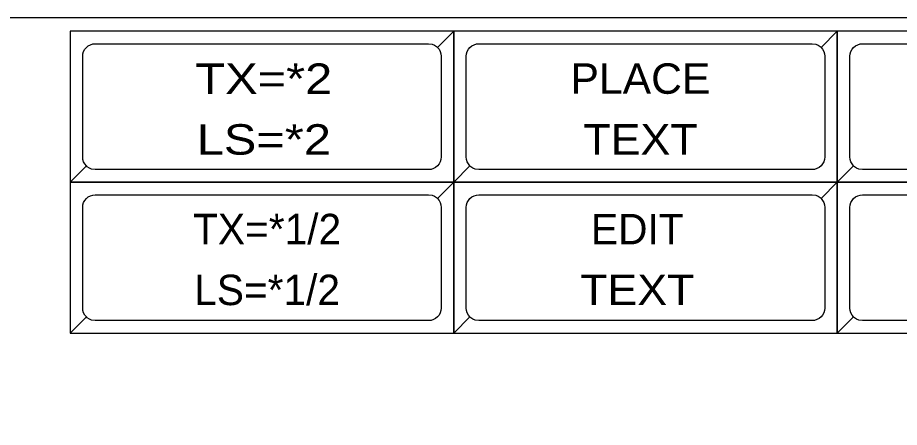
# Model space of a CAD drawing. Extents: x 16898 to 16911.6, y 15837.8 to 15842.
# Drawn here: x 16905.198 to 16906.776, y 15841.28 to 15842.012 of the extents above; entities that cross this region are included whole.
import ezdxf
from ezdxf.enums import TextEntityAlignment as Align

# ---------------------------------------------------------------- set-up
doc = ezdxf.new("R2010")
doc.units = 0
doc.header["$LTSCALE"] = 0.018
for name, color, linetype, lineweight in [('1', 7, 'Continuous', 25), ('2', 7, 'Continuous', 13), ('5', 7, 'Continuous', 13)]:
    doc.layers.add(name, color=color, linetype=linetype, lineweight=lineweight)

msp = doc.modelspace()

# ---------------------------------------------------------------- linework, layer by layer
at = {"layer": '1'}
for points in [[(16897.9955, 15839.9723), (16897.9955, 15842.0124), (16911.4764, 15842.0124), (16911.5674, 15841.9251), (16911.5674, 15840.0599), (16911.4764, 15839.9723)], [(16905.292, 15841.7183), (16905.9784, 15841.7183), (16905.9784, 15841.9883), (16905.292, 15841.9883)], [(16905.292, 15841.7183), (16905.9784, 15841.7183), (16905.9784, 15841.9883), (16905.9493, 15841.9592), (16905.9521, 15841.9558), (16905.9542, 15841.9519), (16905.9554, 15841.9477), (16905.9559, 15841.9433), (16905.9559, 15841.7633), (16905.9554, 15841.7589), (16905.9542, 15841.7547), (16905.9521, 15841.7508), (16905.9493, 15841.7474), (16905.9493, 15841.7474), (16905.9459, 15841.7446), (16905.942, 15841.7425), (16905.9378, 15841.7412), (16905.9334, 15841.7408), (16905.337, 15841.7408), (16905.3304, 15841.7418), (16905.3264, 15841.7435), (16905.3227, 15841.7459), (16905.3211, 15841.7474)], [(16905.9784, 15841.9883), (16905.292, 15841.9883), (16905.292, 15841.7183), (16905.3211, 15841.7474), (16905.3183, 15841.7508), (16905.3162, 15841.7547), (16905.3149, 15841.7589), (16905.3145, 15841.7633), (16905.3145, 15841.9433), (16905.3149, 15841.9477), (16905.3162, 15841.9519), (16905.3183, 15841.9558), (16905.3211, 15841.9592), (16905.3211, 15841.9592), (16905.3245, 15841.962), (16905.3284, 15841.9641), (16905.3326, 15841.9653), (16905.337, 15841.9658), (16905.9334, 15841.9658), (16905.94, 15841.9648), (16905.944, 15841.9631), (16905.9477, 15841.9607), (16905.9493, 15841.9592)], [(16905.9784, 15841.7183), (16906.6648, 15841.7183), (16906.6648, 15841.9883), (16905.9784, 15841.9883)], [(16905.9784, 15841.7183), (16906.6648, 15841.7183), (16906.6648, 15841.9883), (16906.6357, 15841.9592), (16906.6385, 15841.9558), (16906.6406, 15841.9519), (16906.6418, 15841.9477), (16906.6423, 15841.9433), (16906.6423, 15841.7633), (16906.6418, 15841.7589), (16906.6406, 15841.7547), (16906.6385, 15841.7508), (16906.6357, 15841.7474), (16906.6357, 15841.7474), (16906.6323, 15841.7446), (16906.6284, 15841.7425), (16906.6242, 15841.7412), (16906.6198, 15841.7408), (16906.0234, 15841.7408), (16906.0168, 15841.7418), (16906.0128, 15841.7435), (16906.0091, 15841.7459), (16906.0075, 15841.7474)], [(16906.6648, 15841.9883), (16905.9784, 15841.9883), (16905.9784, 15841.7183), (16906.0075, 15841.7474), (16906.0047, 15841.7508), (16906.0026, 15841.7547), (16906.0013, 15841.7589), (16906.0009, 15841.7633), (16906.0009, 15841.9433), (16906.0013, 15841.9477), (16906.0026, 15841.9519), (16906.0047, 15841.9558), (16906.0075, 15841.9592), (16906.0075, 15841.9592), (16906.0109, 15841.962), (16906.0148, 15841.9641), (16906.019, 15841.9653), (16906.0234, 15841.9658), (16906.6198, 15841.9658), (16906.6264, 15841.9648), (16906.6304, 15841.9631), (16906.6341, 15841.9607), (16906.6357, 15841.9592)], [(16906.6648, 15841.7183), (16907.3512, 15841.7183), (16907.3512, 15841.9883), (16906.6648, 15841.9883)], [(16906.6648, 15841.7183), (16907.3512, 15841.7183), (16907.3512, 15841.9883), (16907.3221, 15841.9592), (16907.3249, 15841.9558), (16907.327, 15841.9519), (16907.3282, 15841.9477), (16907.3287, 15841.9433), (16907.3287, 15841.7633), (16907.3282, 15841.7589), (16907.327, 15841.7547), (16907.3249, 15841.7508), (16907.3221, 15841.7474), (16907.3221, 15841.7474), (16907.3187, 15841.7446), (16907.3148, 15841.7425), (16907.3106, 15841.7412), (16907.3062, 15841.7408), (16906.7098, 15841.7408), (16906.7032, 15841.7418), (16906.6992, 15841.7435), (16906.6955, 15841.7459), (16906.6939, 15841.7474)], [(16907.3512, 15841.9883), (16906.6648, 15841.9883), (16906.6648, 15841.7183), (16906.6939, 15841.7474), (16906.6911, 15841.7508), (16906.689, 15841.7547), (16906.6877, 15841.7589), (16906.6873, 15841.7633), (16906.6873, 15841.9433), (16906.6877, 15841.9477), (16906.689, 15841.9519), (16906.6911, 15841.9558), (16906.6939, 15841.9592), (16906.6939, 15841.9592), (16906.6973, 15841.962), (16906.7012, 15841.9641), (16906.7054, 15841.9653), (16906.7098, 15841.9658), (16907.3062, 15841.9658), (16907.3128, 15841.9648), (16907.3168, 15841.9631), (16907.3205, 15841.9607), (16907.3221, 15841.9592)], [(16905.292, 15841.4483), (16905.9784, 15841.4483), (16905.9784, 15841.7183), (16905.292, 15841.7183)], [(16905.292, 15841.4483), (16905.9784, 15841.4483), (16905.9784, 15841.7183), (16905.9493, 15841.6892), (16905.9521, 15841.6858), (16905.9542, 15841.6819), (16905.9554, 15841.6777), (16905.9559, 15841.6733), (16905.9559, 15841.4933), (16905.9554, 15841.4889), (16905.9542, 15841.4847), (16905.9521, 15841.4808), (16905.9493, 15841.4774), (16905.9493, 15841.4774), (16905.9459, 15841.4746), (16905.942, 15841.4725), (16905.9378, 15841.4712), (16905.9334, 15841.4708), (16905.337, 15841.4708), (16905.3304, 15841.4718), (16905.3264, 15841.4735), (16905.3227, 15841.4759), (16905.3211, 15841.4774)], [(16905.9784, 15841.7183), (16905.292, 15841.7183), (16905.292, 15841.4483), (16905.3211, 15841.4774), (16905.3183, 15841.4808), (16905.3162, 15841.4847), (16905.3149, 15841.4889), (16905.3145, 15841.4933), (16905.3145, 15841.6733), (16905.3149, 15841.6777), (16905.3162, 15841.6819), (16905.3183, 15841.6858), (16905.3211, 15841.6892), (16905.3211, 15841.6892), (16905.3245, 15841.692), (16905.3284, 15841.6941), (16905.3326, 15841.6953), (16905.337, 15841.6958), (16905.9334, 15841.6958), (16905.94, 15841.6948), (16905.944, 15841.6931), (16905.9477, 15841.6907), (16905.9493, 15841.6892)], [(16905.9784, 15841.4483), (16906.6648, 15841.4483), (16906.6648, 15841.7183), (16905.9784, 15841.7183)], [(16905.9784, 15841.4483), (16906.6648, 15841.4483), (16906.6648, 15841.7183), (16906.6357, 15841.6892), (16906.6385, 15841.6858), (16906.6406, 15841.6819), (16906.6418, 15841.6777), (16906.6423, 15841.6733), (16906.6423, 15841.4933), (16906.6418, 15841.4889), (16906.6406, 15841.4847), (16906.6385, 15841.4808), (16906.6357, 15841.4774), (16906.6357, 15841.4774), (16906.6323, 15841.4746), (16906.6284, 15841.4725), (16906.6242, 15841.4712), (16906.6198, 15841.4708), (16906.0234, 15841.4708), (16906.0168, 15841.4718), (16906.0128, 15841.4735), (16906.0091, 15841.4759), (16906.0075, 15841.4774)], [(16906.6648, 15841.7183), (16905.9784, 15841.7183), (16905.9784, 15841.4483), (16906.0075, 15841.4774), (16906.0047, 15841.4808), (16906.0026, 15841.4847), (16906.0013, 15841.4889), (16906.0009, 15841.4933), (16906.0009, 15841.6733), (16906.0013, 15841.6777), (16906.0026, 15841.6819), (16906.0047, 15841.6858), (16906.0075, 15841.6892), (16906.0075, 15841.6892), (16906.0109, 15841.692), (16906.0148, 15841.6941), (16906.019, 15841.6953), (16906.0234, 15841.6958), (16906.6198, 15841.6958), (16906.6264, 15841.6948), (16906.6304, 15841.6931), (16906.6341, 15841.6907), (16906.6357, 15841.6892)], [(16906.6648, 15841.4483), (16907.3512, 15841.4483), (16907.3512, 15841.7183), (16906.6648, 15841.7183)], [(16906.6648, 15841.4483), (16907.3512, 15841.4483), (16907.3512, 15841.7183), (16907.3221, 15841.6892), (16907.3249, 15841.6858), (16907.327, 15841.6819), (16907.3282, 15841.6777), (16907.3287, 15841.6733), (16907.3287, 15841.4933), (16907.3282, 15841.4889), (16907.327, 15841.4847), (16907.3249, 15841.4808), (16907.3221, 15841.4774), (16907.3221, 15841.4774), (16907.3187, 15841.4746), (16907.3148, 15841.4725), (16907.3106, 15841.4712), (16907.3062, 15841.4708), (16906.7098, 15841.4708), (16906.7032, 15841.4718), (16906.6992, 15841.4735), (16906.6955, 15841.4759), (16906.6939, 15841.4774)], [(16907.3512, 15841.7183), (16906.6648, 15841.7183), (16906.6648, 15841.4483), (16906.6939, 15841.4774), (16906.6911, 15841.4808), (16906.689, 15841.4847), (16906.6877, 15841.4889), (16906.6873, 15841.4933), (16906.6873, 15841.6733), (16906.6877, 15841.6777), (16906.689, 15841.6819), (16906.6911, 15841.6858), (16906.6939, 15841.6892), (16906.6939, 15841.6892), (16906.6973, 15841.692), (16906.7012, 15841.6941), (16906.7054, 15841.6953), (16906.7098, 15841.6958), (16907.3062, 15841.6958), (16907.3128, 15841.6948), (16907.3168, 15841.6931), (16907.3205, 15841.6907), (16907.3221, 15841.6892)]]:
    msp.add_lwpolyline(points, close=True, dxfattribs=at)
at = {"layer": '2'}
msp.add_lwpolyline([(16897.9955, 15839.9723), (16897.9955, 15842.0124), (16911.4764, 15842.0124), (16911.5674, 15841.9251), (16911.5674, 15840.0599), (16911.4764, 15839.9723)], close=True, dxfattribs=at)

# ---------------------------------------------------------------- texts
at = {"layer": '5'}
for s, width, p in [('TX=*2', 1.2, (16905.6385, 15841.8761)), ('PLACE', 1.05, (16906.3125, 15841.8763)), ('LS=*2', 1.2, (16905.6386, 15841.7675)), ('TEXT', 1.1, (16906.3126, 15841.7676)), ('TEXT', 1.1, (16906.3069, 15841.4987))]:
    msp.add_text(s, height=0.0544, dxfattribs=dict(at, width=width)).set_placement(p, align=Align.CENTER)
for s, p in [('TX=*1/2', (16905.6445, 15841.6073)), ('EDIT', (16906.3069, 15841.6072)), ('LS=*1/2', (16905.6445, 15841.4985))]:
    msp.add_text(s, height=0.0544, dxfattribs=at).set_placement(p, align=Align.CENTER)

doc.saveas('drawing.dxf')
